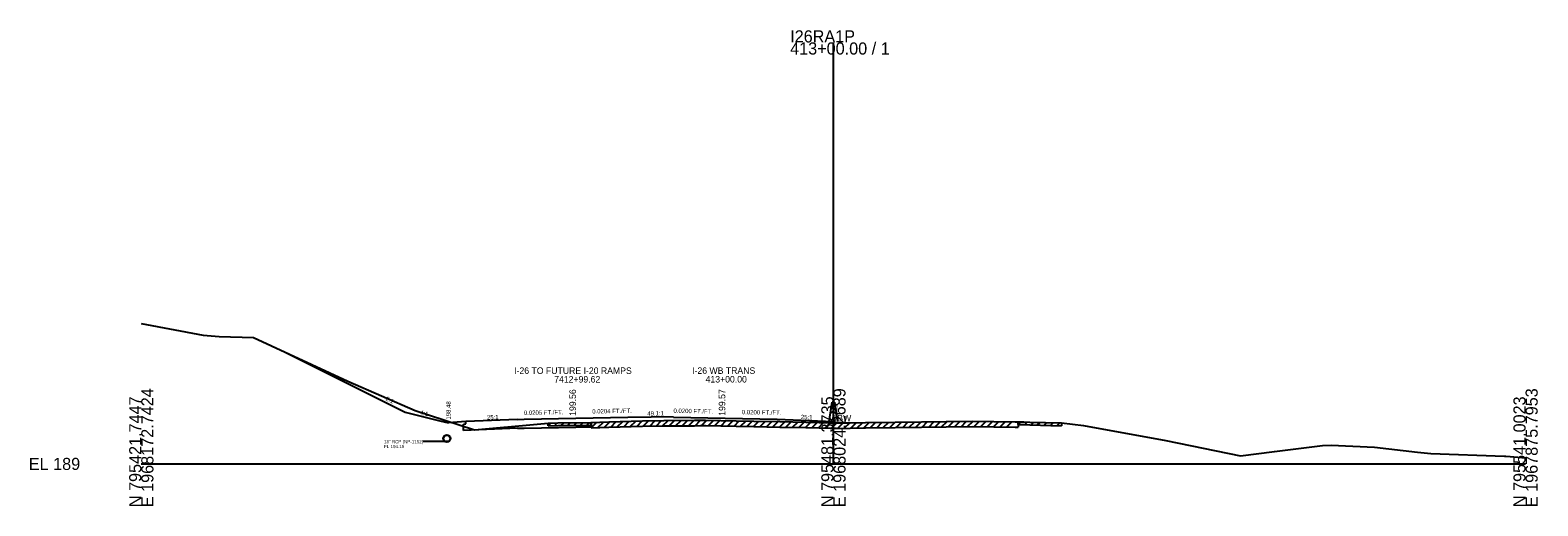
# Model space of a CAD drawing. Extents: x -44 to 4323, y -10 to 9601.
# Drawn here: x -25.7 to 322.8, y 7990.3 to 8100.3 of the extents above; entities that cross this region are included whole.
import ezdxf

# ---------------------------------------------------------------- set-up
doc = ezdxf.new("R2010")
doc.units = 0
for name, color, linetype in [('1', 7, 'Continuous'), ('DateStamp', 7, 'Continuous'), ('NotForConst', 7, 'Continuous'), ('QCQA', 7, 'Continuous'), ('RD_SHT_Bndy', 7, 'Continuous'), ('RD_SHT_Iplotshp', 7, 'Continuous'), ('RD_SHT_TX', 7, 'Continuous'), ('RD_TX_Misc1', 7, 'Continuous'), ('RD_XS_ExGround', 7, 'Continuous'), ('RD_XS_Misc_Line', 7, 'Continuous'), ('RD_XS_Pave', 7, 'Continuous'), ('RD_XS_PaveShd', 7, 'Continuous'), ('RD_XS_Pipe', 7, 'Continuous'), ('RD_XS_TX_Elev_PR', 7, 'Continuous'), ('RD_XS_TX_Profile', 7, 'Continuous'), ('RD_XS_TX_ShdSlope', 7, 'Continuous'), ('RD_XS_TX_Slope', 7, 'Continuous'), ('seal', 7, 'Continuous'), ('TR SN EXTRUDED PANEL SIGNS - GROUND MOUNTED', 7, 'Continuous')]:
    doc.layers.add(name, color=color, linetype=linetype)

msp = doc.modelspace()

# ---------------------------------------------------------------- linework, layer by layer
at = {"layer": 'DateStamp'}
msp.add_lwpolyline([(0, 8032.48), (14.31, 8029.8), (18.02, 8029.49), (25.97, 8029.25), (47.71, 8019.12), (63.29, 8012.34), (76.99, 8007.89), (79.6, 8008.13), (88.94, 8008.97), (94.02, 8009.43), (96.29, 8009.48), (103.89, 8009.6), (108.05, 8009.73), (115.89, 8009.97), (120.8, 8010.02), (127.85, 8010.09), (129.27, 8010.1), (130.42, 8010.1), (137.52, 8009.96), (141.6, 8009.89), (147.59, 8009.77), (153.63, 8009.64), (156.67, 8009.57), (159.25, 8009.5), (160, 8009.49), (160.68, 8009.49), (161.9, 8009.47), (163.87, 8009.52), (167.45, 8009.6), (174.27, 8009.68), (180.36, 8009.76), (186.09, 8009.82), (192.17, 8009.88), (201.99, 8009.75), (204, 8009.73), (205.41, 8009.69), (212.71, 8009.46), (217.8, 8008.9), (236.85, 8005.38), (254.14, 8001.84), (261.95, 8002.86), (273.06, 8004.23), (275.06, 8004.31), (285.08, 8003.9), (295.01, 8002.75), (298.14, 8002.42), (315.11, 8001.81), (315.47, 8001.81), (316.43, 8001.71), (320, 8001.43)], dxfattribs=at)
at = {"layer": 'NotForConst'}
for p, q in [((94.02, 8008.81), (94.65, 8009.45)), ((95.52, 8008.84), (96.15, 8009.48)), ((97.02, 8008.86), (97.65, 8009.5)), ((98.52, 8008.89), (99.15, 8009.53)), ((100.02, 8008.91), (100.65, 8009.55)), ((101.52, 8008.94), (102.15, 8009.58)), ((103.02, 8008.97), (103.65, 8009.6)), ((104.02, 8008.36), (105.31, 8009.65)), ((105.52, 8008.4), (106.81, 8009.69)), ((107.02, 8008.45), (108.31, 8009.74)), ((108.52, 8008.49), (109.81, 8009.78)), ((110.02, 8008.54), (111.31, 8009.83)), ((111.52, 8008.59), (112.81, 8009.88)), ((113.02, 8008.63), (114.31, 8009.92)), ((114.52, 8008.68), (115.81, 8009.97)), ((116.02, 8008.72), (117.28, 8009.98)), ((117.52, 8008.74), (118.78, 8010)), ((119.02, 8008.75), (120.28, 8010.02)), ((120.52, 8008.77), (121.78, 8010.03)), ((122.02, 8008.78), (123.28, 8010.04)), ((123.52, 8008.8), (124.78, 8010.06)), ((125.02, 8008.81), (126.28, 8010.07)), ((126.52, 8008.83), (127.78, 8010.09)), ((128.02, 8008.84), (129.27, 8010.1)), ((129.52, 8008.85), (130.76, 8010.09)), ((131.02, 8008.84), (132.24, 8010.06)), ((132.52, 8008.81), (133.74, 8010.04)), ((134.02, 8008.78), (135.24, 8010.01)), ((135.52, 8008.75), (136.74, 8009.98)), ((137.02, 8008.72), (138.24, 8009.95)), ((138.52, 8008.7), (139.75, 8009.92)), ((140.02, 8008.67), (141.25, 8009.9)), ((141.52, 8008.64), (142.74, 8009.87)), ((143.02, 8008.61), (144.24, 8009.84)), ((144.52, 8008.58), (145.74, 8009.81)), ((146.02, 8008.55), (147.24, 8009.77)), ((147.52, 8008.52), (148.74, 8009.74)), ((149.02, 8008.49), (150.24, 8009.71)), ((150.52, 8008.46), (151.74, 8009.68)), ((152.02, 8008.43), (153.24, 8009.65)), ((153.52, 8008.39), (154.74, 8009.62)), ((155.02, 8008.36), (156.24, 8009.58)), ((156.52, 8008.33), (157.73, 8009.54)), ((158.02, 8008.29), (159.23, 8009.5)), ((159.52, 8008.25), (160.75, 8009.49)), ((161.02, 8008.23), (162.26, 8009.47)), ((162.52, 8008.23), (163.8, 8009.51)), ((164.02, 8008.27), (165.3, 8009.55)), ((165.52, 8008.31), (166.8, 8009.59)), ((167.02, 8008.34), (168.29, 8009.61)), ((168.52, 8008.36), (169.78, 8009.63)), ((170.02, 8008.38), (171.28, 8009.64)), ((171.52, 8008.4), (172.78, 8009.66)), ((173.02, 8008.41), (174.28, 8009.68)), ((174.52, 8008.43), (175.78, 8009.7)), ((176.02, 8008.45), (177.28, 8009.72)), ((177.52, 8008.47), (178.78, 8009.74)), ((179.02, 8008.49), (180.28, 8009.76)), ((180.52, 8008.51), (181.78, 8009.77)), ((182.02, 8008.53), (183.28, 8009.79)), ((183.52, 8008.54), (184.78, 8009.81)), ((185.02, 8008.56), (186.28, 8009.82)), ((186.52, 8008.57), (187.78, 8009.84)), ((188.02, 8008.59), (189.28, 8009.85)), ((189.52, 8008.6), (190.78, 8009.87)), ((191.02, 8008.62), (192.28, 8009.88)), ((192.52, 8008.63), (193.75, 8009.86)), ((194.02, 8008.61), (195.25, 8009.84)), ((195.52, 8008.59), (196.75, 8009.82)), ((197.02, 8008.57), (198.25, 8009.8)), ((198.52, 8008.55), (199.75, 8009.78)), ((200.02, 8008.53), (201.25, 8009.76)), ((202.71, 8009.12), (203.33, 8009.73)), ((204.21, 8009.1), (204.82, 8009.7)), ((205.71, 8009.05), (206.32, 8009.66)), ((207.21, 8009.01), (207.82, 8009.61)), ((208.71, 8008.96), (209.32, 8009.57)), ((210.21, 8008.91), (210.82, 8009.52)), ((211.71, 8008.87), (212.32, 8009.47))]:
    msp.add_line(p, q, dxfattribs=at)
at = {"layer": 'QCQA'}
for p, q in [((104.02, 8009.61), (108.05, 8009.73)), ((104.02, 8009.61), (104.02, 8008.59)), ((108.05, 8009.73), (115.89, 8009.97)), ((115.89, 8009.97), (120.8, 8010.02)), ((120.8, 8010.02), (127.85, 8010.09)), ((127.85, 8010.09), (129.27, 8010.1)), ((129.27, 8010.1), (130.42, 8010.1)), ((130.42, 8010.1), (137.52, 8009.96)), ((137.52, 8009.96), (141.6, 8009.89)), ((141.6, 8009.89), (147.59, 8009.77)), ((147.59, 8009.77), (153.63, 8009.64)), ((153.63, 8009.64), (156.67, 8009.57)), ((156.67, 8009.57), (159.25, 8009.5)), ((159.25, 8009.5), (160, 8009.49))]:
    msp.add_line(p, q, dxfattribs=at)
at = {"layer": 'RD_SHT_Bndy'}
for p, q in [((160, 8000), (160, 8097.44)), ((0, 8000), (160, 8000)), ((160, 8000), (320, 8000))]:
    msp.add_line(p, q, dxfattribs=at)
at = {"layer": 'RD_SHT_Iplotshp'}
for p, q in [((94.02, 8008.81), (94.02, 8009.43)), ((104.02, 8008.36), (104.02, 8009.61)), ((104.02, 8009.61), (104.02, 8008.98)), ((202.71, 8009.74), (202.71, 8008.49)), ((202.71, 8009.12), (202.71, 8009.74)), ((212.71, 8009.46), (212.71, 8008.84)), ((94.02, 8008.81), (96.29, 8008.85)), ((96.29, 8008.85), (103.89, 8008.98)), ((103.89, 8008.98), (104.02, 8008.98)), ((104.02, 8008.36), (108.05, 8008.48)), ((108.05, 8008.48), (115.89, 8008.72)), ((115.89, 8008.72), (120.8, 8008.77)), ((120.8, 8008.77), (127.85, 8008.84)), ((127.85, 8008.84), (129.27, 8008.85)), ((129.27, 8008.85), (130.42, 8008.85)), ((130.42, 8008.85), (137.52, 8008.71)), ((137.52, 8008.71), (141.6, 8008.64)), ((141.6, 8008.64), (147.59, 8008.52)), ((147.59, 8008.52), (153.63, 8008.39)), ((153.63, 8008.39), (156.67, 8008.32)), ((156.67, 8008.32), (159.25, 8008.25)), ((159.25, 8008.25), (160, 8008.24)), ((160, 8008.24), (160.68, 8008.24)), ((160.68, 8008.24), (161.9, 8008.22)), ((161.9, 8008.22), (163.87, 8008.27)), ((163.87, 8008.27), (167.45, 8008.35)), ((167.45, 8008.35), (174.27, 8008.43)), ((174.27, 8008.43), (180.36, 8008.51)), ((180.36, 8008.51), (186.09, 8008.57)), ((186.09, 8008.57), (192.17, 8008.63)), ((192.17, 8008.63), (201.99, 8008.5)), ((201.99, 8008.5), (202.71, 8008.49)), ((202.71, 8009.12), (204, 8009.1)), ((204, 8009.1), (205.41, 8009.06)), ((205.41, 8009.06), (212.71, 8008.84))]:
    msp.add_line(p, q, dxfattribs=at)
at = {"layer": 'RD_TX_Misc1'}
for p in [(69, 8009.98), (73, 8009.64)]:
    msp.add_line(p, (71, 8009.48), dxfattribs=at)
at = {"layer": 'RD_XS_Misc_Line'}
for p, q in [((75, 8009.24), (75, 8009.8)), ((74.5, 8009.22), (75, 8009.24)), ((74.5, 8007.74), (74.5, 8009.22)), ((87, 8008.24), (74.5, 8007.74)), ((87, 8008.24), (88.47, 8008.27)), ((88.47, 8008.27), (100.47, 8008.52)), ((100.47, 8008.52), (104.02, 8008.59))]:
    msp.add_line(p, q, dxfattribs=at)
at = {"layer": 'RD_XS_Pave'}
for p, q in [((33.08, 8025.94), (61, 8011.98)), ((61, 8011.98), (69, 8009.98))]:
    msp.add_line(p, q, dxfattribs=at)
at = {"layer": 'RD_XS_PaveShd'}
msp.add_line((75, 8009.8), (73, 8009.64), dxfattribs=at)
at = {"layer": 'RD_XS_Pipe'}
msp.add_line((70.12, 8005.15), (65.12, 8005.15), dxfattribs=at)
for radius in [0.85, 0.75]:
    msp.add_circle((70.62, 8005.9), radius, dxfattribs=at)
at = {"layer": 'RD_XS_TX_Elev_PR'}
for p, q in [((87, 8010.28), (75, 8009.8)), ((112.48, 8010.8), (117.89, 8010.92)), ((123, 8010.81), (117.89, 8010.92)), ((147, 8010.33), (160, 8009.81)), ((160, 8009.81), (160, 8009.49))]:
    msp.add_line(p, q, dxfattribs=at)
at = {"layer": 'RD_XS_TX_ShdSlope'}
for p, q in [((159, 8009.83), (159.67, 8014.31)), ((160, 8014.31), (159.67, 8014.31)), ((160, 8014.31), (160.33, 8014.31)), ((161, 8009.83), (160.33, 8014.31))]:
    msp.add_line(p, q, dxfattribs=at)
at = {"layer": 'RD_XS_TX_Slope'}
for p, q in [((87, 8010.28), (88.47, 8010.31)), ((88.47, 8010.31), (100.47, 8010.56)), ((100.47, 8010.56), (112.48, 8010.8)), ((123, 8010.81), (135, 8010.57)), ((135, 8010.57), (147, 8010.33))]:
    msp.add_line(p, q, dxfattribs=at)

# ---------------------------------------------------------------- texts
at = {"layer": '1'}
for s, p in [('I-26 TO FUTURE I-20 RAMPS', (86.19, 8020.81)), ('7412+99.62', (95.45, 8018.81)), ('I-26 WB TRANS', (127.33, 8020.82)), ('413+00.00', (130.45, 8018.82))]:
    msp.add_text(s, height=1.5, dxfattribs=at).set_placement(p)
at = {"layer": 'RD_SHT_Bndy'}
for s, p in [('I26RA1P', (150, 8097.44)), ('413+00.00 / 1', (150, 8094.64)), ('EL 189', (-26, 7998.6))]:
    msp.add_text(s, height=2.8, dxfattribs=at).set_placement(p)
for s, p in [('E 1968172.7424', (2.8, 7990)), ('E 1968024.2689', (162.8, 7990)), ('E 1967875.7953', (322.8, 7990)), ('N 795421.7447', (0, 7990)), ('N 795481.3735', (160, 7990)), ('N 795541.0023', (320, 7990))]:
    msp.add_text(s, height=2.8, rotation=90, dxfattribs=at).set_placement(p)
at = {"layer": 'RD_SHT_TX'}
msp.add_text('198.49', height=1, rotation=90, dxfattribs=at).set_placement((161, 8009.49))
at = {"layer": 'RD_XS_ExGround'}
for s, rotation, p in [('25:1', 2.29, (79.93, 8010.24)), ('49.1:1', 1.1676, (116.99, 8011.15)), ('25:1', 357.7094, (152.46, 8010.37))]:
    msp.add_text(s, height=1, rotation=rotation, dxfattribs=at).set_placement(p)
at = {"layer": 'RD_XS_Pipe'}
for s, p in [('18" RCP (NP-1152)', (56.12, 8004.77)), ('FL 194.15', (56.12, 8003.65))]:
    msp.add_text(s, height=0.75, dxfattribs=at).set_placement(p)
at = {"layer": 'RD_XS_TX_Profile'}
msp.add_text('WBW', height=1.5, dxfattribs=at).set_placement((159, 8009.83))
at = {"layer": 'seal'}
for s, p in [(' 199.56', (100.47, 8010.56)), (' 199.57', (135, 8010.57))]:
    msp.add_text(s, height=1.5, rotation=90, dxfattribs=at).set_placement(p)
at = {"layer": 'TR SN EXTRUDED PANEL SIGNS - GROUND MOUNTED'}
for s, rotation, p in [('2:1', 333.4349, (56.39, 8014.75)), ('198.48', 90, (71.49, 8010.26)), ('0.0204 FT./FT.', 1.1676, (104.26, 8011.64)), ('0.0200 FT./FT.', 358.8542, (123.02, 8011.81)), ('4:1', 345.9638, (64.35, 8011.46)), ('0.0205 FT./FT.', 1.1732, (88.45, 8011.31)), ('0.0200 FT./FT.', 358.8542, (138.83, 8011.5))]:
    msp.add_text(s, height=1, rotation=rotation, dxfattribs=at).set_placement(p)

doc.saveas('drawing.dxf')
